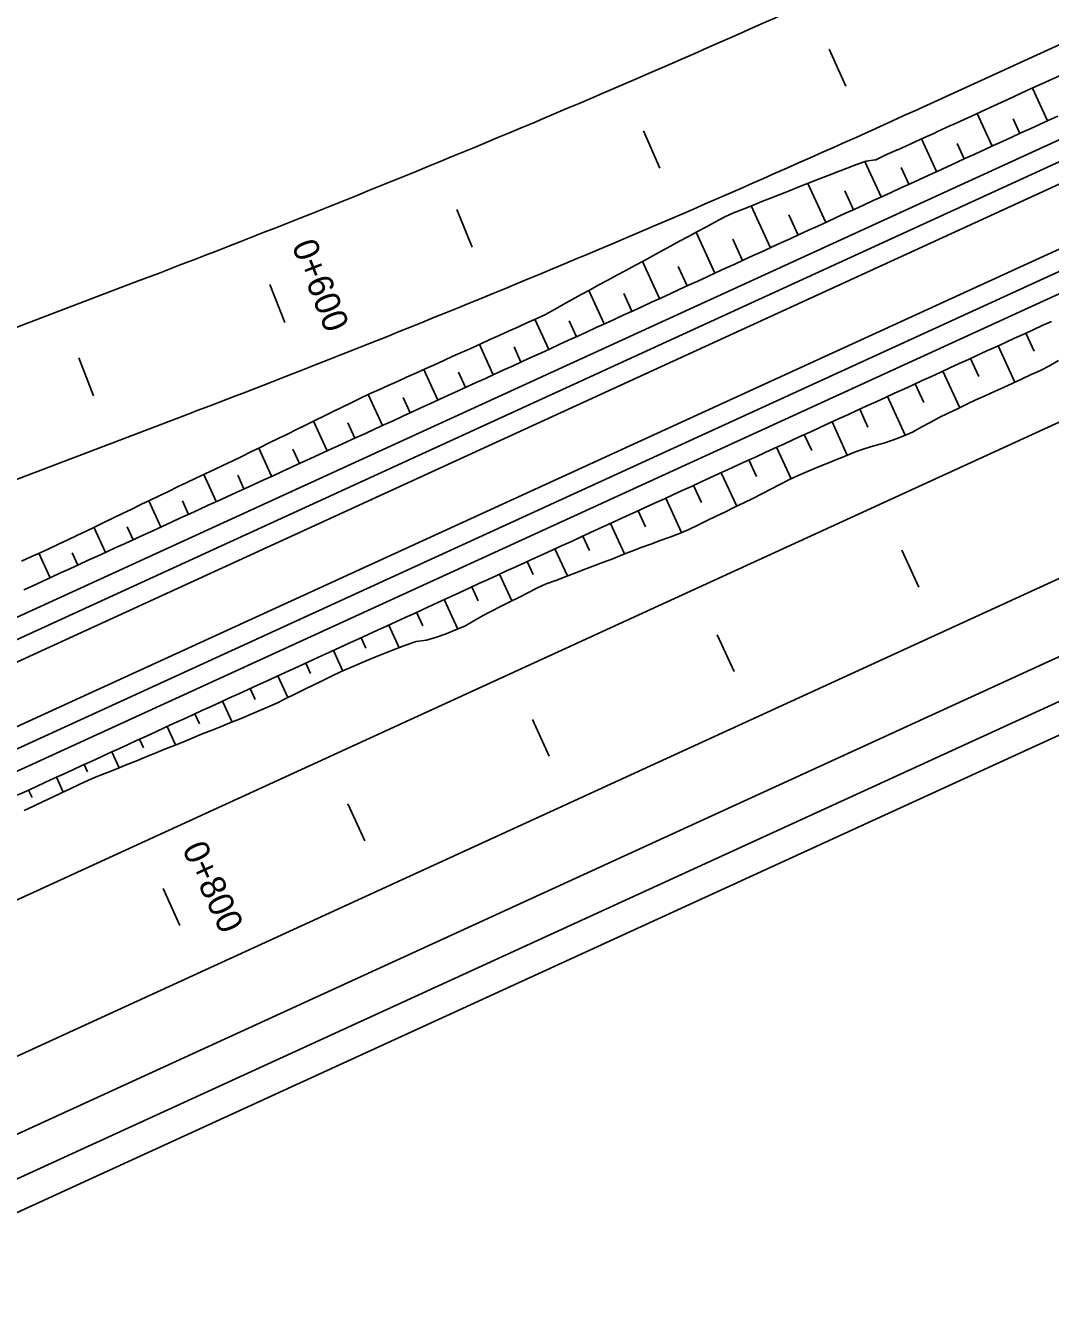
# Model space of a CAD drawing. Extents: x 6503541 to 6503743, y 5888004 to 5888145.
# Drawn here: x 6503610.507 to 6503611.717, y 5888057.597 to 5888059.102 of the extents above; entities that cross this region are included whole.
import ezdxf

# ---------------------------------------------------------------- set-up
doc = ezdxf.new("R2010")
doc.units = 0
doc.layers.add('12', color=7, linetype='Continuous')

msp = doc.modelspace()

# ---------------------------------------------------------------- linework, layer by layer
at = {"layer": '12'}
for p, q in [((6503605.1366, 5888055.919), (6503621.1114, 5888063.2433)), ((6503605.1466, 5888055.8972), (6503621.1214, 5888063.2215)), ((6503605.1756, 5888055.8339), (6503621.1505, 5888063.1582)), ((6503605.1856, 5888055.8121), (6503621.1605, 5888063.1364)), ((6503617.1884, 5888061.5832), (6503611.5845, 5888059.0139)), ((6503617.3575, 5888061.2145), (6503607.3899, 5888056.6445)), ((6503617.4275, 5888061.0618), (6503607.9932, 5888056.7363)), ((6503617.3425, 5888060.9305), (6503607.9659, 5888056.6314)), ((6503617.4389, 5888060.9218), (6503607.9859, 5888056.5878)), ((6503617.4539, 5888060.8891), (6503608.0009, 5888056.555)), ((6503605.811, 5888056.2546), (6503615.7038, 5888060.7903)), ((6503605.6303, 5888055.9895), (6503615.7728, 5888060.6398)), ((6503611.7136, 5888058.9894), (6503611.6959, 5888059.028)), ((6503611.6482, 5888058.9594), (6503611.6305, 5888058.998)), ((6503611.673, 5888058.9917), (6503611.6809, 5888058.9744)), ((6503611.5827, 5888058.9294), (6503611.565, 5888058.968)), ((6503611.6071, 5888058.9626), (6503611.6154, 5888058.9444)), ((6503611.5173, 5888058.8994), (6503611.498, 5888058.9413)), ((6503611.5409, 5888058.9342), (6503611.55, 5888058.9144)), ((6503611.4518, 5888058.8694), (6503611.4307, 5888058.9154)), ((6503611.4744, 5888058.9065), (6503611.4845, 5888058.8844)), ((6503611.3864, 5888058.8394), (6503611.3637, 5888058.8888)), ((6503611.4081, 5888058.8782), (6503611.4191, 5888058.8544)), ((6503611.3209, 5888058.8093), (6503611.2988, 5888058.8577)), ((6503611.3421, 5888058.8496), (6503611.3536, 5888058.8243)), ((6503611.2555, 5888058.7793), (6503611.2353, 5888058.8233)), ((6503611.2776, 5888058.8174), (6503611.2882, 5888058.7943)), ((6503610.3348, 5888058.6842), (6503610.6357, 5888058.7986)), ((6503611.19, 5888058.7493), (6503611.1719, 5888058.7889)), ((6503611.2132, 5888058.7852), (6503611.2227, 5888058.7643)), ((6503611.1246, 5888058.7193), (6503611.1083, 5888058.7548)), ((6503611.1488, 5888058.7529), (6503611.1573, 5888058.7343)), ((6503611.6981, 5888058.7171), (6503611.6883, 5888058.7386)), ((6503611.0591, 5888058.6893), (6503611.0427, 5888058.7252)), ((6503611.0837, 5888058.7221), (6503611.0918, 5888058.7043)), ((6503611.6556, 5888058.7236), (6503611.6753, 5888058.6806)), ((6503611.6327, 5888058.6871), (6503611.6229, 5888058.7086)), ((6503610.9937, 5888058.6593), (6503610.977, 5888058.6956)), ((6503611.0181, 5888058.6923), (6503611.0264, 5888058.6743)), ((6503611.5901, 5888058.6936), (6503611.61, 5888058.6503)), ((6503610.9282, 5888058.6293), (6503610.9114, 5888058.6659)), ((6503611.5676, 5888058.6564), (6503611.5574, 5888058.6786)), ((6503610.9526, 5888058.6625), (6503610.9609, 5888058.6443)), ((6503611.5247, 5888058.6636), (6503611.5457, 5888058.6177)), ((6503610.3945, 5888058.5271), (6503610.6954, 5888058.6415)), ((6503611.5017, 5888058.6272), (6503611.492, 5888058.6486)), ((6503610.8628, 5888058.5993), (6503610.8467, 5888058.6344)), ((6503610.8873, 5888058.6323), (6503610.8955, 5888058.6143)), ((6503611.4592, 5888058.6336), (6503611.4773, 5888058.5942)), ((6503611.4352, 5888058.5996), (6503611.4265, 5888058.6186)), ((6503610.7973, 5888058.5693), (6503610.782, 5888058.6026)), ((6503610.8222, 5888058.6014), (6503610.8301, 5888058.5843)), ((6503611.3938, 5888058.6036), (6503611.4109, 5888058.5662)), ((6503611.3699, 5888058.5692), (6503611.3611, 5888058.5886)), ((6503610.7319, 5888058.5393), (6503610.7172, 5888058.5713)), ((6503610.7572, 5888058.5705), (6503610.7646, 5888058.5543)), ((6503611.3283, 5888058.5735), (6503611.3466, 5888058.5338)), ((6503611.3049, 5888058.5383), (6503611.2956, 5888058.5585)), ((6503610.6664, 5888058.5093), (6503610.6522, 5888058.5403)), ((6503610.6919, 5888058.5401), (6503610.6992, 5888058.5243)), ((6503611.2629, 5888058.5435), (6503611.2816, 5888058.5028)), ((6503611.239, 5888058.5094), (6503611.2302, 5888058.5285)), ((6503610.601, 5888058.4793), (6503610.5873, 5888058.509)), ((6503610.6267, 5888058.5095), (6503610.6337, 5888058.4943)), ((6503611.1974, 5888058.5135), (6503611.2139, 5888058.4775)), ((6503611.1726, 5888058.4814), (6503611.1647, 5888058.4985)), ((6503610.5355, 5888058.4492), (6503610.5222, 5888058.4783)), ((6503610.5616, 5888058.4788), (6503610.5683, 5888058.4643)), ((6503611.132, 5888058.4835), (6503611.1466, 5888058.4516)), ((6503611.1062, 5888058.4533), (6503611.0993, 5888058.4685)), ((6503611.0665, 5888058.4535), (6503611.0809, 5888058.4221)), ((6503611.0414, 5888058.4221), (6503611.0338, 5888058.4385)), ((6503611.0011, 5888058.4235), (6503611.0171, 5888058.3887)), ((6503610.9757, 5888058.3924), (6503610.9684, 5888058.4085)), ((6503610.9356, 5888058.3935), (6503610.9479, 5888058.3667)), ((6503610.9086, 5888058.366), (6503610.9029, 5888058.3785)), ((6503610.8702, 5888058.3635), (6503610.8814, 5888058.3391)), ((6503610.8432, 5888058.3361), (6503610.8375, 5888058.3485)), ((6503610.8047, 5888058.3335), (6503610.8165, 5888058.3077)), ((6503610.7779, 5888058.3056), (6503610.772, 5888058.3185)), ((6503610.7393, 5888058.3035), (6503610.7506, 5888058.2788)), ((6503610.7119, 5888058.2769), (6503610.7066, 5888058.2885)), ((6503610.6739, 5888058.2735), (6503610.6838, 5888058.2518)), ((6503610.6458, 5888058.2484), (6503610.6411, 5888058.2585)), ((6503610.6084, 5888058.2435), (6503610.617, 5888058.2248)), ((6503610.5796, 5888058.2199), (6503610.5757, 5888058.2285)), ((6503610.543, 5888058.2135), (6503610.5509, 5888058.196)), ((6503610.5143, 5888058.1895), (6503610.5102, 5888058.1984))]:
    msp.add_line(p, q, dxfattribs=at)
for points in [[(6503611.4757, 5888059.0303), (6503611.456, 5888059.0741)], [(6503611.51, 5888058.9431), (6503611.5142, 5888058.945), (6503611.5214, 5888058.9483), (6503611.5362, 5888058.955), (6503611.5368, 5888058.9552), (6503611.5523, 5888058.9622), (6503611.5582, 5888058.965), (6503611.5677, 5888058.9693), (6503611.5803, 5888058.975), (6503611.5831, 5888058.9763), (6503611.5985, 5888058.9834), (6503611.6022, 5888058.9851), (6503611.6241, 5888058.9951), (6503611.6459, 5888059.0051), (6503611.6677, 5888059.0151), (6503611.6895, 5888059.0251), (6503611.7113, 5888059.0351), (6503611.7331, 5888059.0451)], [(6503610.5044, 5888058.435), (6503610.5153, 5888058.44), (6503610.5262, 5888058.445), (6503610.5371, 5888058.45), (6503610.548, 5888058.455), (6503610.5589, 5888058.46), (6503610.5698, 5888058.465), (6503610.5807, 5888058.47), (6503610.5916, 5888058.475), (6503610.6025, 5888058.48), (6503610.6134, 5888058.485), (6503610.6243, 5888058.49), (6503610.6353, 5888058.495), (6503610.6462, 5888058.5), (6503610.6571, 5888058.505), (6503610.668, 5888058.51), (6503610.6789, 5888058.515), (6503610.6898, 5888058.52), (6503610.7007, 5888058.525), (6503610.7116, 5888058.53), (6503610.7225, 5888058.535), (6503610.7334, 5888058.54), (6503610.7443, 5888058.545), (6503610.7552, 5888058.55), (6503610.7661, 5888058.555), (6503610.7771, 5888058.56), (6503610.788, 5888058.565), (6503610.7989, 5888058.57), (6503610.8098, 5888058.575), (6503610.8207, 5888058.58), (6503610.8316, 5888058.585), (6503610.8425, 5888058.59), (6503610.8534, 5888058.595), (6503610.8643, 5888058.6), (6503610.8752, 5888058.605), (6503610.8861, 5888058.61), (6503610.897, 5888058.615), (6503610.908, 5888058.62), (6503610.9189, 5888058.625), (6503610.9298, 5888058.63), (6503610.9407, 5888058.635), (6503610.9516, 5888058.64), (6503610.9625, 5888058.645), (6503610.9734, 5888058.65), (6503610.9843, 5888058.655), (6503610.9952, 5888058.66), (6503611.0061, 5888058.665), (6503611.017, 5888058.67), (6503611.0279, 5888058.675), (6503611.0389, 5888058.68), (6503611.0498, 5888058.685), (6503611.0607, 5888058.69), (6503611.0716, 5888058.695), (6503611.0825, 5888058.7), (6503611.0934, 5888058.705), (6503611.1043, 5888058.71), (6503611.1152, 5888058.715), (6503611.1261, 5888058.72), (6503611.137, 5888058.725), (6503611.1479, 5888058.73), (6503611.1588, 5888058.735), (6503611.1698, 5888058.74), (6503611.1807, 5888058.745), (6503611.1916, 5888058.75), (6503611.2025, 5888058.755), (6503611.2134, 5888058.76), (6503611.2243, 5888058.765), (6503611.2352, 5888058.77), (6503611.2461, 5888058.775), (6503611.257, 5888058.78), (6503611.2679, 5888058.785), (6503611.2788, 5888058.79), (6503611.2897, 5888058.795), (6503611.3006, 5888058.8), (6503611.3116, 5888058.805), (6503611.3225, 5888058.8101), (6503611.3334, 5888058.8151), (6503611.3443, 5888058.8201), (6503611.3552, 5888058.8251), (6503611.3661, 5888058.8301), (6503611.377, 5888058.8351), (6503611.3879, 5888058.8401), (6503611.3988, 5888058.8451), (6503611.4097, 5888058.8501), (6503611.4206, 5888058.8551), (6503611.4315, 5888058.8601), (6503611.4425, 5888058.8651), (6503611.4534, 5888058.8701), (6503611.4643, 5888058.8751), (6503611.4752, 5888058.8801), (6503611.4861, 5888058.8851), (6503611.497, 5888058.8901), (6503611.5079, 5888058.8951), (6503611.5188, 5888058.9001), (6503611.5297, 5888058.9051), (6503611.5406, 5888058.9101), (6503611.5515, 5888058.9151), (6503611.5624, 5888058.9201), (6503611.5734, 5888058.9251), (6503611.5843, 5888058.9301), (6503611.5952, 5888058.9351), (6503611.6061, 5888058.9401), (6503611.617, 5888058.9451), (6503611.6279, 5888058.9501), (6503611.6388, 5888058.9551), (6503611.6497, 5888058.9601), (6503611.6606, 5888058.9651), (6503611.6715, 5888058.9701), (6503611.6824, 5888058.9751), (6503611.6933, 5888058.9801), (6503611.7042, 5888058.9851), (6503611.7152, 5888058.9901), (6503611.7261, 5888058.9951)], [(6503611.2557, 5888058.9334), (6503611.2367, 5888058.9775)], [(6503610.502, 5888058.4689), (6503610.5129, 5888058.4739), (6503610.5238, 5888058.479), (6503610.5347, 5888058.484), (6503610.5455, 5888058.4891), (6503610.5564, 5888058.4941), (6503610.5673, 5888058.4993), (6503610.5781, 5888058.5045), (6503610.5889, 5888058.5097), (6503610.5997, 5888058.515), (6503610.6105, 5888058.5202), (6503610.6213, 5888058.5254), (6503610.6321, 5888058.5306), (6503610.6429, 5888058.5358), (6503610.6537, 5888058.541), (6503610.6645, 5888058.5462), (6503610.6754, 5888058.5515), (6503610.6862, 5888058.5567), (6503610.697, 5888058.5618), (6503610.7079, 5888058.5669), (6503610.7187, 5888058.5721), (6503610.7296, 5888058.5772), (6503610.7404, 5888058.5823), (6503610.7513, 5888058.5875), (6503610.762, 5888058.5928), (6503610.7728, 5888058.5981), (6503610.7836, 5888058.6034), (6503610.7943, 5888058.6087), (6503610.8051, 5888058.614), (6503610.8159, 5888058.6192), (6503610.8267, 5888058.6245), (6503610.8374, 5888058.6298), (6503610.8482, 5888058.6351), (6503610.859, 5888058.6404), (6503610.8698, 5888058.6457), (6503610.8805, 5888058.651), (6503610.8913, 5888058.6563), (6503610.9021, 5888058.6616), (6503610.913, 5888058.6667), (6503610.9239, 5888058.6716), (6503610.9348, 5888058.6765), (6503610.9458, 5888058.6815), (6503610.9567, 5888058.6864), (6503610.9677, 5888058.6913), (6503610.9786, 5888058.6963), (6503610.9895, 5888058.7012), (6503611.0005, 5888058.7061), (6503611.0114, 5888058.7111), (6503611.0224, 5888058.716), (6503611.0333, 5888058.7209), (6503611.0442, 5888058.7259), (6503611.0552, 5888058.7308), (6503611.0661, 5888058.7357), (6503611.077, 5888058.7407), (6503611.088, 5888058.7456), (6503611.0989, 5888058.7505), (6503611.1099, 5888058.7555), (6503611.1207, 5888058.7605), (6503611.1313, 5888058.7664), (6503611.1418, 5888058.7723), (6503611.1523, 5888058.7781), (6503611.1628, 5888058.784), (6503611.1734, 5888058.7897), (6503611.1839, 5888058.7955), (6503611.1945, 5888058.8012), (6503611.2051, 5888058.8069), (6503611.2157, 5888058.8126), (6503611.2262, 5888058.8184), (6503611.2368, 5888058.8241), (6503611.2474, 5888058.8298), (6503611.258, 5888058.8356), (6503611.2685, 5888058.8413), (6503611.2791, 5888058.847), (6503611.2897, 5888058.8528), (6503611.3003, 5888058.8585), (6503611.3108, 5888058.8642), (6503611.3214, 5888058.8699), (6503611.332, 5888058.8757), (6503611.3429, 5888058.8805), (6503611.3541, 5888058.885), (6503611.3653, 5888058.8894), (6503611.3764, 5888058.8939), (6503611.3876, 5888058.8983), (6503611.3988, 5888058.9027), (6503611.4099, 5888058.9072), (6503611.4211, 5888058.9116), (6503611.4323, 5888058.9161), (6503611.4434, 5888058.9205), (6503611.4546, 5888058.9249), (6503611.4658, 5888058.9293), (6503611.4771, 5888058.9335), (6503611.4883, 5888058.9377), (6503611.4996, 5888058.9419), (6503611.5101, 5888058.9432)], [(6503611.0342, 5888058.8401), (6503611.0159, 5888058.8845)], [(6503610.7953, 5888058.7959), (6503610.8128, 5888058.7512)], [(6503610.4968, 5888058.1923), (6503610.5077, 5888058.1973), (6503610.5186, 5888058.2023), (6503610.5295, 5888058.2073), (6503610.5404, 5888058.2123), (6503610.5513, 5888058.2173), (6503610.5623, 5888058.2223), (6503610.5732, 5888058.2273), (6503610.5841, 5888058.2323), (6503610.595, 5888058.2373), (6503610.6059, 5888058.2423), (6503610.6168, 5888058.2473), (6503610.6277, 5888058.2523), (6503610.6386, 5888058.2573), (6503610.6495, 5888058.2623), (6503610.6604, 5888058.2673), (6503610.6713, 5888058.2723), (6503610.6822, 5888058.2773), (6503610.6931, 5888058.2823), (6503610.7041, 5888058.2873), (6503610.715, 5888058.2923), (6503610.7259, 5888058.2973), (6503610.7368, 5888058.3023), (6503610.7477, 5888058.3073), (6503610.7586, 5888058.3123), (6503610.7695, 5888058.3173), (6503610.7804, 5888058.3223), (6503610.7913, 5888058.3273), (6503610.8022, 5888058.3323), (6503610.8131, 5888058.3373), (6503610.824, 5888058.3423), (6503610.835, 5888058.3473), (6503610.8459, 5888058.3523), (6503610.8568, 5888058.3573), (6503610.8677, 5888058.3623), (6503610.8786, 5888058.3673), (6503610.8895, 5888058.3723), (6503610.9004, 5888058.3773), (6503610.9113, 5888058.3823), (6503610.9222, 5888058.3873), (6503610.9331, 5888058.3923), (6503610.944, 5888058.3973), (6503610.9549, 5888058.4023), (6503610.9659, 5888058.4073), (6503610.9768, 5888058.4124), (6503610.9877, 5888058.4174), (6503610.9986, 5888058.4224), (6503611.0095, 5888058.4274), (6503611.0204, 5888058.4324), (6503611.0313, 5888058.4374), (6503611.0422, 5888058.4424), (6503611.0531, 5888058.4474), (6503611.064, 5888058.4524), (6503611.0749, 5888058.4574), (6503611.0858, 5888058.4624), (6503611.0967, 5888058.4674), (6503611.1077, 5888058.4724), (6503611.1186, 5888058.4774), (6503611.1295, 5888058.4824), (6503611.1404, 5888058.4874), (6503611.1513, 5888058.4924), (6503611.1622, 5888058.4974), (6503611.1731, 5888058.5024), (6503611.184, 5888058.5074), (6503611.1949, 5888058.5124), (6503611.2058, 5888058.5174), (6503611.2167, 5888058.5224), (6503611.2276, 5888058.5274), (6503611.2386, 5888058.5324), (6503611.2495, 5888058.5374), (6503611.2604, 5888058.5424), (6503611.2713, 5888058.5474), (6503611.2822, 5888058.5524), (6503611.2931, 5888058.5574), (6503611.304, 5888058.5624), (6503611.3149, 5888058.5674), (6503611.3258, 5888058.5724), (6503611.3367, 5888058.5774), (6503611.3476, 5888058.5824), (6503611.3585, 5888058.5874), (6503611.3695, 5888058.5924), (6503611.3804, 5888058.5974), (6503611.3913, 5888058.6024), (6503611.4022, 5888058.6074), (6503611.4131, 5888058.6124), (6503611.424, 5888058.6174), (6503611.4349, 5888058.6224), (6503611.4458, 5888058.6274), (6503611.4567, 5888058.6324), (6503611.4676, 5888058.6374), (6503611.4785, 5888058.6424), (6503611.4894, 5888058.6474), (6503611.5003, 5888058.6524), (6503611.5113, 5888058.6574), (6503611.5222, 5888058.6624), (6503611.5331, 5888058.6674), (6503611.544, 5888058.6724), (6503611.5549, 5888058.6774), (6503611.5658, 5888058.6824), (6503611.5767, 5888058.6874), (6503611.5876, 5888058.6924), (6503611.5985, 5888058.6974), (6503611.6094, 5888058.7024), (6503611.6203, 5888058.7074), (6503611.6312, 5888058.7124), (6503611.6422, 5888058.7174), (6503611.6531, 5888058.7224), (6503611.664, 5888058.7274), (6503611.6749, 5888058.7324), (6503611.6858, 5888058.7374), (6503611.6967, 5888058.7424), (6503611.7076, 5888058.7474), (6503611.7185, 5888058.7524)], [(6503610.5051, 5888058.1742), (6503610.5159, 5888058.1793), (6503610.5268, 5888058.1845), (6503610.5376, 5888058.1897), (6503610.5484, 5888058.1948), (6503610.5593, 5888058.2), (6503610.5701, 5888058.2052), (6503610.581, 5888058.2102), (6503610.5921, 5888058.2147), (6503610.6033, 5888058.2192), (6503610.6144, 5888058.2237), (6503610.6255, 5888058.2282), (6503610.6367, 5888058.2327), (6503610.6478, 5888058.2372), (6503610.6589, 5888058.2417), (6503610.6701, 5888058.2462), (6503610.6812, 5888058.2507), (6503610.6924, 5888058.2552), (6503610.7035, 5888058.2597), (6503610.7146, 5888058.2643), (6503610.7258, 5888058.2688), (6503610.7369, 5888058.2733), (6503610.748, 5888058.2778), (6503610.7592, 5888058.2823), (6503610.7703, 5888058.2868), (6503610.7813, 5888058.2916), (6503610.7923, 5888058.2963), (6503610.8033, 5888058.3012), (6503610.8141, 5888058.3065), (6503610.8248, 5888058.3118), (6503610.8356, 5888058.3171), (6503610.8464, 5888058.3224), (6503610.8571, 5888058.3277), (6503610.8679, 5888058.333), (6503610.8788, 5888058.338), (6503610.8898, 5888058.3429), (6503610.9008, 5888058.3477), (6503610.9118, 5888058.3525), (6503610.923, 5888058.3569), (6503610.9342, 5888058.3613), (6503610.9453, 5888058.3657), (6503610.9565, 5888058.3701), (6503610.968, 5888058.374), (6503610.9804, 5888058.3756), (6503610.9921, 5888058.379), (6503611.0033, 5888058.3832), (6503611.0145, 5888058.3877), (6503611.0256, 5888058.3922), (6503611.036, 5888058.3983), (6503611.0464, 5888058.4044), (6503611.0571, 5888058.4098), (6503611.0677, 5888058.4155), (6503611.0785, 5888058.4209), (6503611.0892, 5888058.4262), (6503611.1, 5888058.4315), (6503611.1107, 5888058.4369), (6503611.1215, 5888058.4421), (6503611.1328, 5888058.4463), (6503611.144, 5888058.4506), (6503611.1553, 5888058.4548), (6503611.1665, 5888058.4591), (6503611.1778, 5888058.4633), (6503611.1891, 5888058.4676), (6503611.2003, 5888058.4718), (6503611.2113, 5888058.4765), (6503611.2226, 5888058.4808), (6503611.2339, 5888058.485), (6503611.2451, 5888058.4892), (6503611.2564, 5888058.4934), (6503611.2678, 5888058.4975), (6503611.279, 5888058.5017), (6503611.29, 5888058.5065), (6503611.3009, 5888058.5117), (6503611.3116, 5888058.5169), (6503611.3224, 5888058.5222), (6503611.3333, 5888058.5274), (6503611.3441, 5888058.5326), (6503611.3549, 5888058.5379), (6503611.3656, 5888058.5431), (6503611.3763, 5888058.5486), (6503611.387, 5888058.554), (6503611.3977, 5888058.5595), (6503611.4084, 5888058.5649), (6503611.4192, 5888058.5704), (6503611.4302, 5888058.5751), (6503611.4413, 5888058.5796), (6503611.4525, 5888058.5841), (6503611.4636, 5888058.5886), (6503611.4747, 5888058.5931), (6503611.4859, 5888058.5976), (6503611.4972, 5888058.6018), (6503611.5088, 5888058.6051), (6503611.5205, 5888058.6085), (6503611.5319, 5888058.6123), (6503611.5432, 5888058.6166), (6503611.5541, 5888058.6216), (6503611.5647, 5888058.6272), (6503611.5753, 5888058.6329), (6503611.5859, 5888058.6386), (6503611.5966, 5888058.644), (6503611.6075, 5888058.6491), (6503611.6183, 5888058.6544), (6503611.6291, 5888058.6595), (6503611.64, 5888058.6644), (6503611.651, 5888058.6694), (6503611.6619, 5888058.6744), (6503611.6728, 5888058.6794), (6503611.6837, 5888058.6845), (6503611.6946, 5888058.6895), (6503611.7055, 5888058.6944), (6503611.7162, 5888058.6999), (6503611.7266, 5888058.7061)], [(6503610.5868, 5888058.6644), (6503610.5697, 5888058.7093)], [(6503611.5616, 5888058.4384), (6503611.5416, 5888058.482)], [(6503611.3435, 5888058.3384), (6503611.3235, 5888058.382)], [(6503611.1253, 5888058.2384), (6503611.1053, 5888058.282)], [(6503610.9072, 5888058.1383), (6503610.8872, 5888058.182)], [(6503610.669, 5888058.0819), (6503610.689, 5888058.0383)]]:
    msp.add_lwpolyline(points, dxfattribs=at)
for radius in [14.316, 14.484]:
    msp.add_arc((6503605.548, 5888072.18), radius, 290.81698, 294.63106, dxfattribs=at)

# ---------------------------------------------------------------- texts
for s, rotation, p in [('0+600', 291.4078, (6503610.8206, 5888058.8422)), ('0+800', 294.6311, (6503610.691, 5888058.1292))]:
    msp.add_text(s, height=0.03, rotation=rotation, dxfattribs=at).set_placement(p)

doc.saveas('drawing.dxf')
